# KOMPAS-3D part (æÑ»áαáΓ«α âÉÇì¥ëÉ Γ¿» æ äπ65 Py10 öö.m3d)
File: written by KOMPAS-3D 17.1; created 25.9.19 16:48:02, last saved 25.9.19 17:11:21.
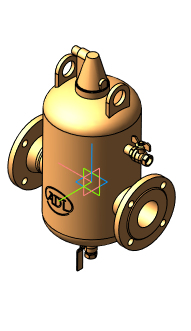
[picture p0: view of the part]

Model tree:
1. Операция без истории:3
